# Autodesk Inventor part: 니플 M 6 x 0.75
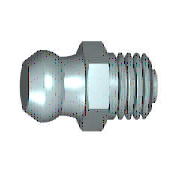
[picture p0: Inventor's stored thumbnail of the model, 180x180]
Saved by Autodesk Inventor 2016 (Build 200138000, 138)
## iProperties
IsCustomPart: 1
Created: 2012-02
Part Number: 니플 M 6 x 0.75
Material: 강철, 연강
Description: 윤활 니플, 원추 유형 A
Document SubType Name: Modeling
Standard: JIS B 1575
Designer: mduedu
Standards Organization: JIS
Language: ko-KR
Size Designation: MT 6 x 0.75
Categories: <MemberInstance><Categories><Category DisplayName="기타 부품" InternalName="5aa15e00-363f-49f2-933f-16f664388e3f" Mnemonic="OTHER"><Category DisplayName="그리스 부속품" I
Density: 1 g/cm^3
Appearance: 강철
Author: mduedu
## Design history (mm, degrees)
sketch "스케치1"
  geometry: L1 (-8.8, 0)-(-8.8, 2.4); L2 (-8.8, 2.4)-(-7.335, 3.202); L3 (-8.8, 0)-(4.7, 0); L4 (4.7, 0)-(4.7, 1.5); L5 (4.7, 1.5)-(4, 1.5); L6 (4, 1.5)-(4, 3); L7 (4, 3)-(0, 3); L8 (-11.5, 0)-(7.4, 0) reference; L9 (0, -1.733)-(0, 10.398) reference; L10 (-3, 3.5)-(0, 3.5); L11 (0, 3.5)-(0, 3); A1 r 3.3 centre (-6.535, 0) between (-4.789, 2.8) and (-7.335, 3.202); A2 r 6 centre (-6.053, 8.665) between (-4.789, 2.8) and (-3, 3.5)
  constraints: 18 end point, 5 perpendicular, 4 point on circle, 2 centre point, 2 parallel, 2 point on line, 1 collinear, 1 vertical
  dimensions: "d0" = 13.5 distance between parallel lines of L1 L4 (= GL); "d1" = 5.6 diameter of A1.start L3 (= KGB2); "d2" = 0.7 distance between parallel lines of L4 L6 (= PHH); "d3" = 3 diameter of L5 L3 (= 0.5 x NND); "d4" = 6 diameter of L7 L3 (= NND); "d5" = 6.6 dimension on A1 L3 (= KR); "d6" = 4.8 diameter of L1.end L3 (= KGB1); "d7" = 6 radius of A2 (= RBN); "d11" = 7 diameter of L10.start L3 (= SW); "d14" = 3 distance of L10.start L10.end (= KOH); "d15" = 4 distance between parallel lines of L6 L11 (= NLG); "d61" = 7.33505 distance from line of L9 L2.end (computed from KGB1, KR, PHH, GL, NLG, VERS); "d62" = 6.53505 distance from line of L9 A1.centre (computed from NLG, GL, PHH, KR, KGB1)
revolve "본체" sketch "스케치1" stored, may be unused: angle "d25" = 90 deg
sketch "스케치2"
  geometry: L1 (2.021, 3.5)-(4.041, 0); L2 (4.041, 0)-(2.021, -3.5); L3 (2.021, -3.5)-(-2.021, -3.5); L4 (-2.021, -3.5)-(-4.041, 0); L5 (-4.041, 0)-(-2.021, 3.5); L6 (-2.021, 3.5)-(2.021, 3.5); C1 r 3.5 at (0, 0) reference; 1 further point
  constraints: 12 end point, 1 coincident, 1 horizontal, 1 tangent, 11 other
extrude "머리" join sketch "스케치2" distance "d17" = 3 (= KOH); taper "d18" = 0 deg
sketch "스케치3"
  geometry: L1 (2.687, 4.041)-(3, 4.041); L2 (3, 4.041)-(3, 3.5); L3 (3, 3.5)-(2.687, 4.041); L4 (0.313, 4.041)-(0, 4.041); L5 (0, 4.041)-(0, 3.5); L6 (0, 3.5)-(0.313, 4.041); L7 (3.6, 0)-(-0.6, 0) reference; L8 (0, 4.041)-(0, 2.021) reference; L9 (0, 4.041)-(3, 4.041) reference; L10 (3, 3.031)-(3, 4.041) reference
  constraints: 12 end point, 4 collinear, 3 perpendicular, 1 horizontal
  dimensions: "d19" = 3.5 distance from line of L5.end L7 (= 0.5 x SW); "d20" = 3.5 distance from line of L2.end L7 (= 0.5 x SW); "d21" = 30 deg angle of L6 L5; "d22" = 30 deg angle of L2 L3
revolve "모따기1" sketch "스케치3" stored, may be unused: angle "d56" = 90 deg
body "Solid1"
fillet "모깎기1" dims "d8" = 0.2 (= RR)
feature "스레드1" dims "d9" = 3.53991 (= NLG - GAL), "d10" = 0
chamfer "모따기2" distance "d23" = 0.46009 (= -0.5 x GD1 + 0.5 x NND); stored, may be unused: angle "d24" = 45 deg, second distance "d59" = 0.46009 (= -0.5 x GD1 + 0.5 x NND)
other parameters: "NLG" = 4 [user parameter; used in 4 equation terms], "GL" = 13.5 [user parameter; used in 3 equation terms], "NND" = 6 [user parameter; used in 4 equation terms], "KGB1" = 4.8 [user parameter; used in 3 equation terms], "KGB2" = 5.6 [user parameter; used in 1 equation term], "VERS" = 0.8 [user parameter; used in 1 equation term], "KR" = 6.6 [user parameter; used in 3 equation terms], "RBN" = 6 [user parameter; used in 1 equation term], "SW" = 7 [user parameter; used in 3 equation terms], "KOH" = 3 [user parameter; used in 2 equation terms], "GAL" = 0.46009 (= 0.61345 x PTC) [user parameter; used in 1 equation term], "FAWI" = 45 deg [user parameter], "PHH" = 0.7 [user parameter; used in 3 equation terms], "GD1" = 5.07983 (= THREADDIA - 1.2269 x PTC) [user parameter; used in 2 equation terms], "RR" = 0.2 [user parameter; used in 1 equation term], "d12" = 0, "d13" = 0, "GUL" = 0.46009 (= 0.61345 x PTC) [user parameter], "TPU" = 13.33333 (computed from PTC) [user parameter], "DULO" = 1.5 [user parameter], "PTC" = 0.75 [user parameter; used in 4 equation terms], "GEL" = 4 [user parameter], "THREADDIA" = 6 [user parameter; used in 1 equation term], "TOA" = 30 deg [user parameter]
